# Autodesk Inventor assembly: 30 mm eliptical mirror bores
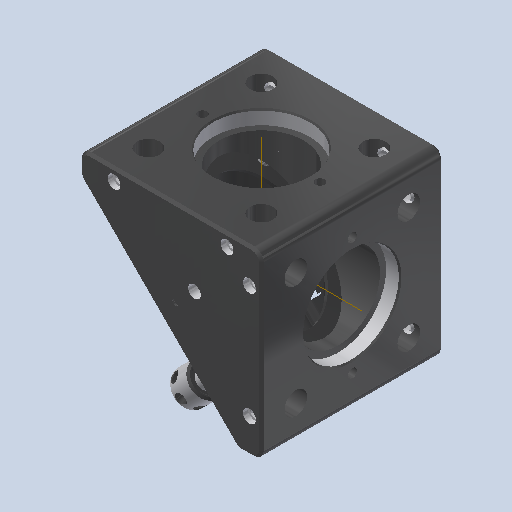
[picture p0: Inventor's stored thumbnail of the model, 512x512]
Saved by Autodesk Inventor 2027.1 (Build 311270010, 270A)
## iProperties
Created: 2017-01
Part Number: 30 mm eliptical mirror bores
Document SubType Name: Assembly
Designer: Radek
Author: Radek
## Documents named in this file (2)
- C:\Users\dunge\OneDrive\Documents\Inventor\Inventor\Inventor\simplified-drawings\imports\30 mm eliptical mirror bores.iam
- C:\Users\dunge\OneDrive\Documents\Inventor\Inventor\Inventor\1p2p\imported\rotation mounts\KCB1EC_M-Solidworks.ipt
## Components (1 placed, 1 different names)
1. KCB1EC_M-Solidworks:1 — Mate:2, Mate:3
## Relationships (2: Mate 2)
- Mate:2: KCB1EC_M-Solidworks:1
- Mate:3: KCB1EC_M-Solidworks:1
